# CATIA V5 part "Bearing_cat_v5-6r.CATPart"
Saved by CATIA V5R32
Part number: Bearing
Bounding box of the stored display mesh (mm): x -10 to 10, y -17.5 to 17.5, z -17.322 to 17.322
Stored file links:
  D:\PROJECTS\Project 2022\CATIA V5 6R 2022\Resources\Tutorial Files\c16_catia_v5_6r2022_tut\Cam Follower mechanism\Bearing_cat_v5-6r.CATPart
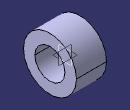
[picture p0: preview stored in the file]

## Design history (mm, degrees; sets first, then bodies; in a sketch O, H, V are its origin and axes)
Body1 (main body)
  Sketch1 on yz-plane, origin (0, 0, 0), H (0, 1, 0), V (0, 0, 1)
    circle A1 centre (0, 0) radius 10
    circle A2 centre (0, 0) radius 17.5
    radius A1 = 10
    radius A2 = 17.5
  Pad1: profile Sketch1, direction (1, 0, 0), length 10, mirrored extent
